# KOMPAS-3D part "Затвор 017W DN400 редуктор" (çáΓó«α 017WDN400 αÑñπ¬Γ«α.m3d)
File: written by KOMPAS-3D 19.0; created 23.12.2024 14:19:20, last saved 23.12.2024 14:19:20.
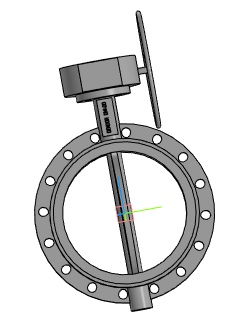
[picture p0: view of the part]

Document properties: Автор: Евгений; Полное имя файла: ..\Затвор 017WDN400 редуктор.a3d

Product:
- Part/product: Затвор 017W DN400 редуктор
    Масса: 133.618

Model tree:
1. Операция без истории:1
